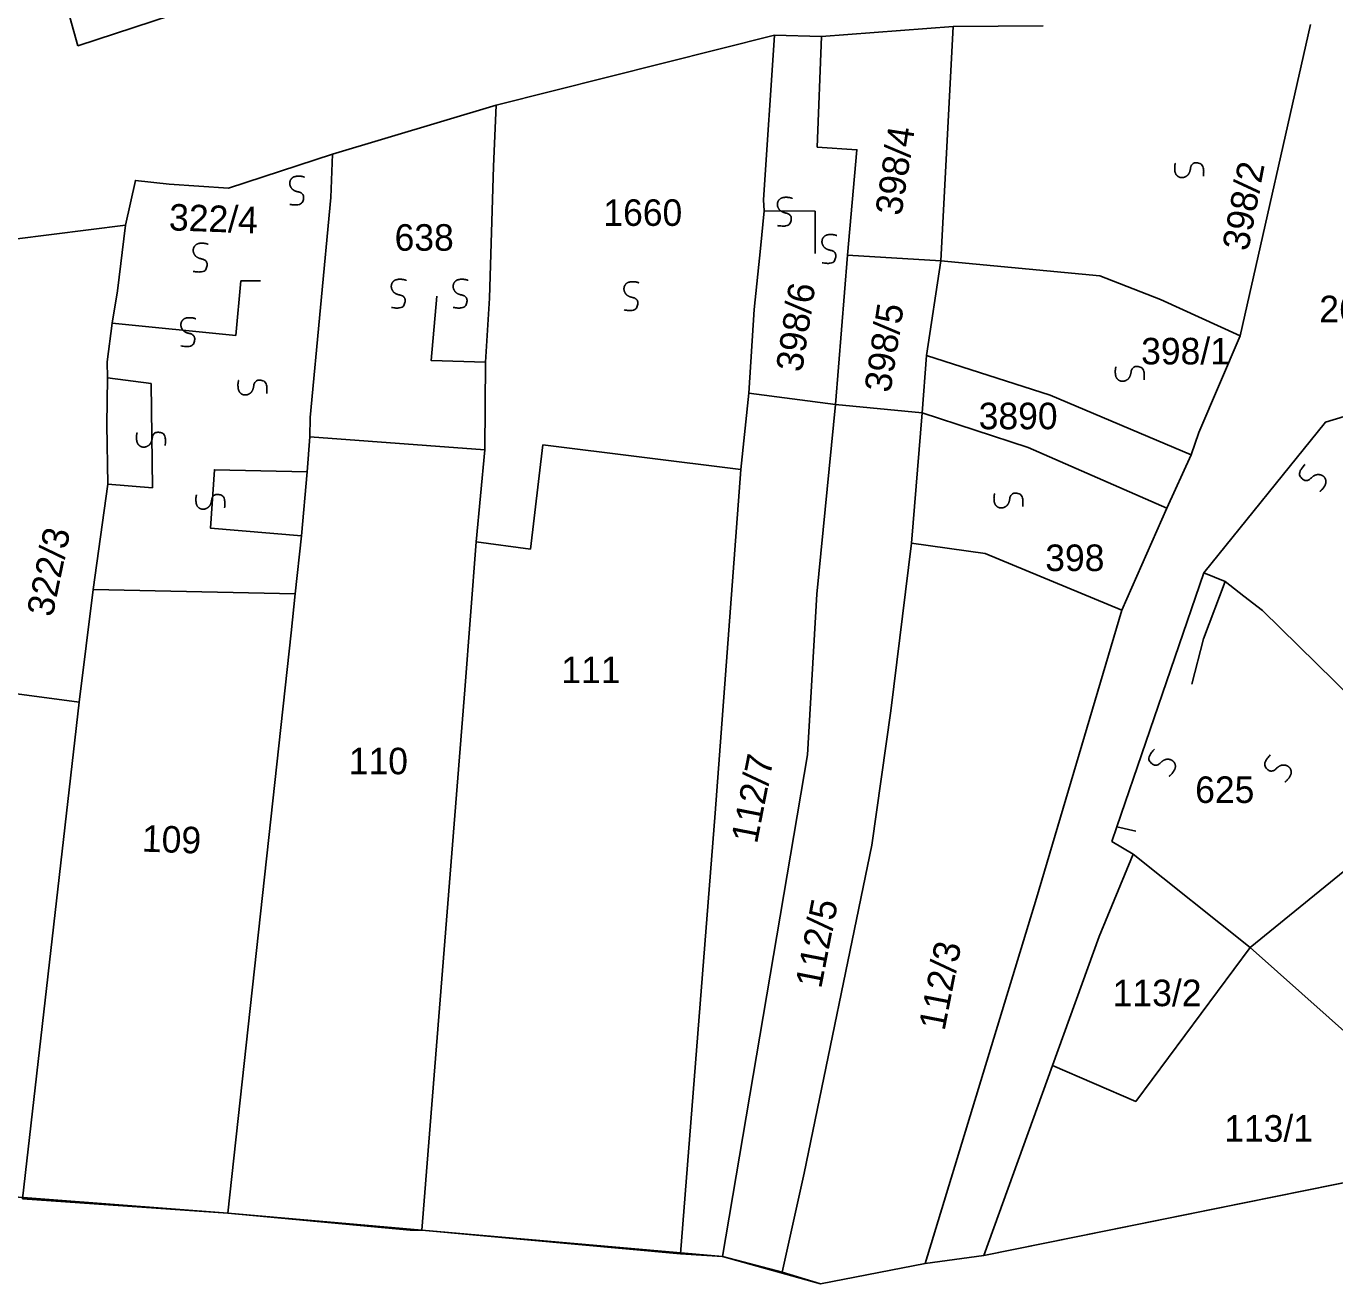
# Model space of a CAD drawing. Extents: x -581999 to -572728, y -1219553 to -1212032.
# Drawn here: x -577759.4 to -577660.7, y -1215973.7 to -1215878.9 of the extents above; entities that cross this region are included whole.
import ezdxf

# ---------------------------------------------------------------- set-up
doc = ezdxf.new("R2010")
doc.units = 0
for name, color, linetype in [('Vrstva 1', 7, 'Continuous'), ('Vrstva 2', 7, 'Continuous'), ('Vrstva 4', 7, 'Continuous'), ('Vrstva 6', 7, 'Continuous'), ('Vrstva 63', 7, 'Continuous')]:
    doc.layers.add(name, color=color, linetype=linetype)

msp = doc.modelspace()

# ---------------------------------------------------------------- linework, layer by layer
at = {"layer": 'Vrstva 1'}
for p, q in [((-577757.159, -1215874.414), (-577755.494, -1215880.34)), ((-577755.494, -1215880.34), (-577740.35, -1215875.383)), ((-577682.711, -1215878.838), (-577689.49, -1215878.903)), ((-577736.413, -1215891.788), (-577736.293, -1215888.523)), ((-577691.505, -1215903.685), (-577682.174, -1215906.679)), ((-577704.897, -1215906.519), (-577705.501, -1215912.295)), ((-577682.174, -1215906.679), (-577671.537, -1215911.172)), ((-577720.43, -1215910.423), (-577721.363, -1215918.284)), ((-577705.501, -1215912.295), (-577720.43, -1215910.423)), ((-577725.469, -1215917.723), (-577724.811, -1215910.805)), ((-577705.501, -1215912.295), (-577707.427, -1215938.181)), ((-577726.323, -1215928.894), (-577725.469, -1215917.723)), ((-577721.363, -1215918.284), (-577725.469, -1215917.723)), ((-577668.991, -1215920.736), (-577670.598, -1215920.058)), ((-577667.586, -1215921.82), (-577668.991, -1215920.736)), ((-577765.023, -1215928.534), (-577755.392, -1215929.815)), ((-577729.558, -1215969.621), (-577726.323, -1215928.894)), ((-577652.555, -1215936.446), (-577667.09, -1215948.308)), ((-577707.427, -1215938.181), (-577710.061, -1215971.406))]:
    msp.add_line(p, q, dxfattribs=at)
for points in [[(-577667.844, -1215902.215), (-577662.549, -1215878.75)], [(-577723.959, -1215884.828), (-577702.962, -1215879.549)], [(-577702.962, -1215879.549), (-577703.781, -1215891.968), (-577703.743, -1215892.797)], [(-577699.413, -1215879.656), (-577702.962, -1215879.549)], [(-577697.454, -1215896.122), (-577696.751, -1215888.179), (-577699.736, -1215887.978), (-577699.413, -1215879.656)], [(-577699.413, -1215879.656), (-577689.49, -1215878.903)], [(-577689.49, -1215878.903), (-577690.427, -1215896.559)], [(-577744.118, -1215891.091), (-577736.293, -1215888.523), (-577723.959, -1215884.828)], [(-577723.959, -1215884.828), (-577724.141, -1215889.441)], [(-577724.141, -1215889.441), (-577724.453, -1215899.374)], [(-577744.118, -1215891.091), (-577748.61, -1215890.769), (-577751.15, -1215890.494), (-577751.899, -1215893.877)], [(-577738.005, -1215909.808), (-577737.972, -1215908.364), (-577736.413, -1215891.788)], [(-577703.743, -1215892.797), (-577704.008, -1215895.636), (-577704.487, -1215900.214)], [(-577751.899, -1215893.877), (-577763.072, -1215895.262), (-577765.204, -1215895.788)], [(-577752.496, -1215898.824), (-577751.899, -1215893.877)], [(-577698.367, -1215907.385), (-577697.454, -1215896.122)], [(-577690.427, -1215896.559), (-577697.454, -1215896.122)], [(-577690.427, -1215896.559), (-577691.505, -1215903.685), (-577691.82, -1215908.003)], [(-577678.425, -1215897.698), (-577690.427, -1215896.559)], [(-577673.87, -1215899.465), (-577678.425, -1215897.698)], [(-577753.249, -1215905.385), (-577753.286, -1215904.16), (-577752.902, -1215901.251), (-577752.496, -1215898.824)], [(-577724.453, -1215899.374), (-577724.745, -1215904.204)], [(-577667.844, -1215902.215), (-577673.87, -1215899.465)], [(-577704.487, -1215900.214), (-577704.897, -1215906.519)], [(-577673.385, -1215915.201), (-577671.537, -1215911.172), (-577670.977, -1215909.487), (-577667.844, -1215902.215)], [(-577724.745, -1215904.204), (-577724.811, -1215910.805)], [(-577753.303, -1215908.915), (-577753.249, -1215905.385)], [(-577698.367, -1215907.385), (-577704.897, -1215906.519)], [(-577675.915, -1215941.265), (-577677.522, -1215940.316), (-577677.146, -1215939.226), (-577670.598, -1215920.058), (-577661.429, -1215908.722), (-577657.513, -1215907.544), (-577652.711, -1215906.469)], [(-577706.888, -1215971.604), (-577700.483, -1215933.799), (-577699.761, -1215921.676), (-577698.367, -1215907.385)], [(-577691.82, -1215908.003), (-577698.367, -1215907.385)], [(-577691.82, -1215908.003), (-577692.638, -1215917.843)], [(-577683.832, -1215910.636), (-577691.82, -1215908.003)], [(-577753.223, -1215913.379), (-577753.303, -1215908.915)], [(-577738.005, -1215909.808), (-577738.203, -1215912.453)], [(-577724.811, -1215910.805), (-577738.005, -1215909.808)], [(-577673.385, -1215915.201), (-577683.832, -1215910.636)], [(-577754.328, -1215921.32), (-577753.223, -1215913.379)], [(-577738.203, -1215912.453), (-577738.631, -1215917.282)], [(-577676.769, -1215922.89), (-577673.385, -1215915.201)], [(-577738.631, -1215917.282), (-577739.108, -1215921.642)], [(-577692.638, -1215917.843), (-577694.184, -1215930.466)], [(-577687.084, -1215918.605), (-577692.638, -1215917.843)], [(-577676.769, -1215922.89), (-577687.084, -1215918.605)], [(-577754.328, -1215921.32), (-577755.392, -1215929.815)], [(-577739.108, -1215921.642), (-577754.328, -1215921.32)], [(-577739.108, -1215921.642), (-577739.408, -1215924.6)], [(-577658.032, -1215930.895), (-577666.182, -1215922.904), (-577667.586, -1215921.82)], [(-577683.211, -1215944.6), (-577676.769, -1215922.89)], [(-577744.192, -1215968.334), (-577739.408, -1215924.6)], [(-577755.392, -1215929.815), (-577759.67, -1215967.247)], [(-577694.184, -1215930.466), (-577695.613, -1215940.6), (-577700.717, -1215965.316), (-577702.382, -1215972.778)], [(-577682.016, -1215957.199), (-577678.49, -1215947.476), (-577675.915, -1215941.265)], [(-577667.09, -1215948.308), (-577675.915, -1215941.265)], [(-577691.598, -1215972.118), (-577683.211, -1215944.6)], [(-577682.016, -1215957.199), (-577675.722, -1215959.912), (-577667.09, -1215948.308)], [(-577649.451, -1215964.013), (-577667.09, -1215948.308)], [(-577687.172, -1215971.51), (-577682.016, -1215957.199)], [(-577687.172, -1215971.51), (-577653.343, -1215964.682), (-577649.451, -1215964.013)], [(-577759.67, -1215967.247), (-577744.192, -1215968.334)], [(-577744.192, -1215968.334), (-577730.425, -1215969.619), (-577729.558, -1215969.621)], [(-577710.061, -1215971.406), (-577729.558, -1215969.621)], [(-577710.061, -1215971.406), (-577706.888, -1215971.604)], [(-577702.382, -1215972.778), (-577706.888, -1215971.604)], [(-577691.598, -1215972.118), (-577687.172, -1215971.51)], [(-577702.382, -1215972.778), (-577699.498, -1215973.656), (-577691.598, -1215972.118)]]:
    msp.add_lwpolyline(points, dxfattribs=at)
at = {"layer": 'Vrstva 4'}
for p, q in [((-577703.743, -1215892.797), (-577699.907, -1215892.805)), ((-577699.903, -1215896.01), (-577699.907, -1215892.805)), ((-577743.571, -1215902.187), (-577743.198, -1215898.069)), ((-577743.198, -1215898.069), (-577741.705, -1215898.069)), ((-577752.902, -1215901.251), (-577743.571, -1215902.187)), ((-577668.991, -1215920.736), (-577670.608, -1215925.056)), ((-577670.608, -1215925.056), (-577671.51, -1215928.466)), ((-577675.729, -1215939.534), (-577677.146, -1215939.226))]:
    msp.add_line(p, q, dxfattribs=at)
for points in [[(-577724.745, -1215904.204), (-577728.855, -1215904.057), (-577728.426, -1215899.229)], [(-577749.962, -1215905.806), (-577753.249, -1215905.385)], [(-577749.853, -1215913.671), (-577749.962, -1215905.806)], [(-577738.631, -1215917.282), (-577745.48, -1215916.715), (-577745.19, -1215912.301), (-577738.203, -1215912.453)], [(-577753.223, -1215913.379), (-577749.853, -1215913.671)]]:
    msp.add_lwpolyline(points, dxfattribs=at)
at = {"layer": 'Vrstva 6'}
for points in [[(-577670.625, -1215890.171), (-577670.53, -1215889.32), (-577671.26, -1215889.108), (-577671.577, -1215889.362), (-577671.622, -1215889.778), (-577671.773, -1215890.085), (-577672.022, -1215890.252), (-577672.249, -1215890.296), (-577672.512, -1215890.24), (-577672.767, -1215889.976), (-577672.807, -1215889.366), (-577672.737, -1215889.197)], [(-577739.506, -1215892.298), (-577738.665, -1215892.45), (-577738.402, -1215891.736), (-577738.634, -1215891.402), (-577739.046, -1215891.329), (-577739.342, -1215891.157), (-577739.492, -1215890.896), (-577739.52, -1215890.667), (-577739.446, -1215890.409), (-577739.165, -1215890.173), (-577738.553, -1215890.175), (-577738.39, -1215890.257)], [(-577702.74, -1215893.892), (-577701.899, -1215894.044), (-577701.636, -1215893.33), (-577701.868, -1215892.996), (-577702.28, -1215892.923), (-577702.576, -1215892.751), (-577702.726, -1215892.49), (-577702.754, -1215892.261), (-577702.68, -1215892.003), (-577702.399, -1215891.767), (-577701.787, -1215891.769), (-577701.624, -1215891.851)], [(-577699.381, -1215896.699), (-577698.54, -1215896.851), (-577698.277, -1215896.137), (-577698.509, -1215895.803), (-577698.921, -1215895.73), (-577699.217, -1215895.558), (-577699.367, -1215895.297), (-577699.395, -1215895.068), (-577699.321, -1215894.81), (-577699.04, -1215894.574), (-577698.428, -1215894.576), (-577698.265, -1215894.658)], [(-577746.785, -1215897.352), (-577745.944, -1215897.504), (-577745.681, -1215896.79), (-577745.913, -1215896.456), (-577746.325, -1215896.383), (-577746.621, -1215896.211), (-577746.771, -1215895.95), (-577746.799, -1215895.721), (-577746.725, -1215895.463), (-577746.444, -1215895.227), (-577745.832, -1215895.229), (-577745.669, -1215895.311)], [(-577731.852, -1215900.069), (-577731.011, -1215900.221), (-577730.748, -1215899.507), (-577730.98, -1215899.173), (-577731.392, -1215899.1), (-577731.688, -1215898.928), (-577731.838, -1215898.667), (-577731.866, -1215898.438), (-577731.792, -1215898.18), (-577731.511, -1215897.944), (-577730.899, -1215897.946), (-577730.736, -1215898.028)], [(-577727.187, -1215900.069), (-577726.346, -1215900.221), (-577726.083, -1215899.507), (-577726.315, -1215899.173), (-577726.727, -1215899.1), (-577727.023, -1215898.928), (-577727.173, -1215898.667), (-577727.201, -1215898.438), (-577727.127, -1215898.18), (-577726.846, -1215897.944), (-577726.234, -1215897.946), (-577726.071, -1215898.028)], [(-577714.31, -1215900.256), (-577713.469, -1215900.408), (-577713.206, -1215899.694), (-577713.438, -1215899.36), (-577713.85, -1215899.287), (-577714.146, -1215899.115), (-577714.296, -1215898.854), (-577714.324, -1215898.625), (-577714.25, -1215898.367), (-577713.969, -1215898.131), (-577713.357, -1215898.133), (-577713.194, -1215898.215)], [(-577747.718, -1215902.967), (-577746.877, -1215903.119), (-577746.614, -1215902.405), (-577746.846, -1215902.071), (-577747.258, -1215901.998), (-577747.554, -1215901.826), (-577747.704, -1215901.565), (-577747.732, -1215901.336), (-577747.658, -1215901.078), (-577747.377, -1215900.842), (-577746.765, -1215900.844), (-577746.602, -1215900.926)], [(-577675.104, -1215905.52), (-577675.009, -1215904.669), (-577675.739, -1215904.457), (-577676.056, -1215904.711), (-577676.101, -1215905.127), (-577676.252, -1215905.434), (-577676.501, -1215905.601), (-577676.728, -1215905.645), (-577676.991, -1215905.589), (-577677.246, -1215905.325), (-577677.286, -1215904.715), (-577677.216, -1215904.546)], [(-577741.25, -1215906.553), (-577741.155, -1215905.702), (-577741.885, -1215905.49), (-577742.202, -1215905.744), (-577742.247, -1215906.16), (-577742.398, -1215906.467), (-577742.647, -1215906.634), (-577742.874, -1215906.678), (-577743.137, -1215906.622), (-577743.392, -1215906.358), (-577743.432, -1215905.748), (-577743.362, -1215905.579)], [(-577748.902, -1215910.483), (-577748.807, -1215909.632), (-577749.537, -1215909.42), (-577749.854, -1215909.674), (-577749.899, -1215910.09), (-577750.05, -1215910.397), (-577750.299, -1215910.564), (-577750.526, -1215910.608), (-577750.789, -1215910.552), (-577751.044, -1215910.288), (-577751.084, -1215909.678), (-577751.014, -1215909.509)], [(-577662.961, -1215911.897), (-577663.548, -1215912.519), (-577663.093, -1215913.128), (-577662.687, -1215913.116), (-577662.401, -1215912.811), (-577662.095, -1215912.657), (-577661.795, -1215912.673), (-577661.588, -1215912.775), (-577661.412, -1215912.978), (-577661.367, -1215913.342), (-577661.702, -1215913.854), (-577661.86, -1215913.946)], [(-577744.423, -1215915.163), (-577744.328, -1215914.312), (-577745.058, -1215914.1), (-577745.375, -1215914.354), (-577745.42, -1215914.77), (-577745.571, -1215915.077), (-577745.82, -1215915.244), (-577746.047, -1215915.288), (-577746.31, -1215915.232), (-577746.565, -1215914.968), (-577746.605, -1215914.358), (-577746.535, -1215914.189)], [(-577684.248, -1215915.067), (-577684.153, -1215914.216), (-577684.883, -1215914.004), (-577685.2, -1215914.258), (-577685.245, -1215914.674), (-577685.396, -1215914.981), (-577685.645, -1215915.148), (-577685.872, -1215915.192), (-577686.135, -1215915.136), (-577686.39, -1215914.872), (-577686.43, -1215914.262), (-577686.36, -1215914.093)], [(-577674.31, -1215933.35), (-577674.897, -1215933.972), (-577674.442, -1215934.581), (-577674.036, -1215934.569), (-577673.75, -1215934.264), (-577673.444, -1215934.11), (-577673.144, -1215934.126), (-577672.937, -1215934.228), (-577672.761, -1215934.431), (-577672.716, -1215934.795), (-577673.051, -1215935.307), (-577673.209, -1215935.399)], [(-577665.58, -1215933.787), (-577666.167, -1215934.409), (-577665.712, -1215935.018), (-577665.306, -1215935.006), (-577665.02, -1215934.701), (-577664.714, -1215934.547), (-577664.414, -1215934.563), (-577664.207, -1215934.665), (-577664.031, -1215934.868), (-577663.986, -1215935.232), (-577664.321, -1215935.744), (-577664.479, -1215935.836)]]:
    msp.add_open_spline(points, degree=2, dxfattribs=at)
at = {"layer": 'Vrstva 63'}
for p, q in [((-577687.172, -1215971.51), (-577653.343, -1215964.682)), ((-577780.377, -1215965.562), (-577744.192, -1215968.334)), ((-577744.192, -1215968.334), (-577729.558, -1215969.621)), ((-577729.558, -1215969.621), (-577706.888, -1215971.604)), ((-577706.888, -1215971.604), (-577699.498, -1215973.656)), ((-577691.598, -1215972.118), (-577687.172, -1215971.51)), ((-577699.498, -1215973.656), (-577691.598, -1215972.118))]:
    msp.add_line(p, q, dxfattribs=at)

# ---------------------------------------------------------------- texts
at = {"layer": 'Vrstva 2'}
for s, rotation, p in [('398/4', 81.21401, (-577693.402, -1215893.218)), ('398/2', 79.17272, (-577667.256, -1215895.885)), ('322/4', 357.98341, (-577748.642, -1215894.255)), ('398/6', 81.21401, (-577700.891, -1215905.001)), ('398/5', 81.21401, (-577694.226, -1215906.551)), ('322/3', 78.35009, (-577757.396, -1215923.463)), ('112/7', 78.99263, (-577704.283, -1215940.545)), ('109', 357.98341, (-577750.688, -1215941.078)), ('112/5', 78.99263, (-577699.447, -1215951.46)), ('112/3', 78.99263, (-577690.144, -1215954.648))]:
    msp.add_text(s, height=2, rotation=rotation, dxfattribs=at).set_placement(p)
for s, p in [('1660', (-577715.867, -1215893.922)), ('638', (-577731.608, -1215895.794)), ('2619/2', (-577661.89, -1215901.183)), ('398/1', (-577675.319, -1215904.361)), ('3890', (-577687.568, -1215909.249)), ('398', (-577682.55, -1215919.936)), ('111', (-577719.033, -1215928.38)), ('110', (-577735.061, -1215935.254)), ('625', (-577671.246, -1215937.414)), ('113/2', (-577677.462, -1215952.731)), ('113/1', (-577669.056, -1215962.943))]:
    msp.add_text(s, height=2, dxfattribs=at).set_placement(p)

doc.saveas('drawing.dxf')
